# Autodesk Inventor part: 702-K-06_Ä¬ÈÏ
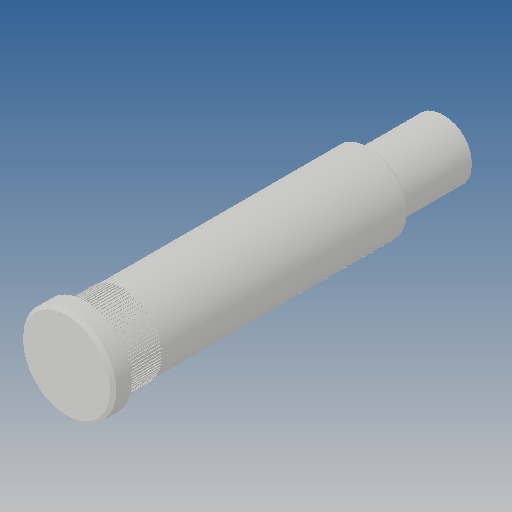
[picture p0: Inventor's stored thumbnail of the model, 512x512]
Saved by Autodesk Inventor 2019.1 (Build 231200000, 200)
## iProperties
Created: 2010-06
Part Number: 702-K-06_Ä¬ÈÏ
Material: Ogólny
Document SubType Name: Modeling
Designer: CADENGINEERING4
Density: 1 g/cm^3
Appearance: Domyślna
Author: CADENGINEERING4
Revision Number: ÈÎºÎ
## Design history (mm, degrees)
feature "NONE"
node "Bryła1"
